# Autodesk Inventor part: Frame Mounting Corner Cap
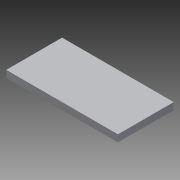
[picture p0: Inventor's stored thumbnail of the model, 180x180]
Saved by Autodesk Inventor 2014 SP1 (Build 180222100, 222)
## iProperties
Created: 2014-11
Part Number: Frame Mounting Corner Cap
Material: Aluminum 6061
Document SubType Name: Sheet Metal
Designer: Michael
Density: 2.71 g/cm^3
Sheet Metal Rule: Default
Appearance: Aluminum - Flat
Author: Michael
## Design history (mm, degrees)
node "Face1"
  sketch "Sketch1"
    geometry: L1 (-25.4, -12.7)-(25.4, -12.7); L2 (25.4, -12.7)-(25.4, 12.7); L3 (25.4, 12.7)-(-25.4, 12.7); L4 (-25.4, 12.7)-(-25.4, -12.7); L5 (-25.4, -12.7)-(25.4, 12.7); L6 (25.4, -12.7)-(-25.4, 12.7); 1 further point
    constraints: 12 end point, 2 midpoint, 2 parallel, 1 horizontal, 1 perpendicular
    dimensions: "d0" = 50.8 distance of L3.end L2.end; "d1" = 25.4 distance of L2.end L1.end
body "Solid1"
face "Plate1" dims "Thickness" = 3.175 (derived)
other parameters: "KFactor" = 4.4, "BendRadius" = 3.175 (= Thickness), "BendReliefWidth" = 3.175 (= Thickness), "BendReliefDepth" = 1.5875 (= 0.5 x Thickness), "CornerReliefSize" = 12.7 (= 4 x Thickness), "SeamGap" = 0.00508, "MinimumRemnant" = 6.35 (= 2 x Thickness), "TransitionRadius" = 3.175 (= BendRadius), "JacobiRadiusSize" = 3.175 (= Thickness), "GapSize" = 3.175 (= Thickness), "d2" = 3.175 (= BendRadius)
